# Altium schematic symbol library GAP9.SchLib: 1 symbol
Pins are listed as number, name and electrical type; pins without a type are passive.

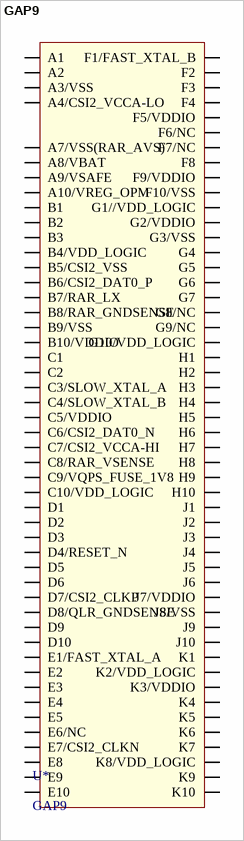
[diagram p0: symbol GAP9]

## GAP9
designator U*
footprint GAP9
pins: A1, A2, A3 A3/VSS, A4 A4/CSI2_VCCA-LO, A7 A7/VSS(RAR_AVS), A8 A8/VBAT, A9 A9/VSAFE, A10 A10/VREG_OPM, B1, B2, B3, B4 B4/VDD_LOGIC, B5 B5/CSI2_VSS, B6 B6/CSI2_DAT0_P, B7 B7/RAR_LX, B8 B8/RAR_GNDSENSE, B9 B9/VSS, B10 B10/VDDIO, C1, C2, C3 C3/SLOW_XTAL_A, C4 C4/SLOW_XTAL_B, C5 C5/VDDIO, C6 C6/CSI2_DAT0_N, C7 C7/CSI2_VCCA-HI, C8 C8/RAR_VSENSE, C9 C9/VQPS_FUSE_1V8, C10 C10/VDD_LOGIC, D1, D2, D3, D4 D4/RESET_N, D5, D6, D7 D7/CSI2_CLKP, D8 D8/QLR_GNDSENSE, D9, D10, E1 E1/FAST_XTAL_A, E2, E3, E4, E5, E6 E6/NC, E7 E7/CSI2_CLKN, E8, E9, E10, F1 F1/FAST_XTAL_B, F2, F3, F4, F5 F5/VDDIO, F6 F6/NC, F7 F7/NC, F8, F9 F9/VDDIO, F10 F10/VSS, G1 G1//VDD_LOGIC, G2 G2/VDDIO, G3 G3/VSS, G4, G5, G6, G7, G8 G8/NC, G9 G9/NC, G10 G10/VDD_LOGIC, H1, H2, H3, H4, H5, H6, H7, H8, H9, H10, J1, J2, J3, J4, J5, J6, J7 J7/VDDIO, J8 J8/VSS, J9, J10, K1, K2 K2/VDD_LOGIC, K3 K3/VDDIO, K4, K5, K6, K7, K8 K8/VDD_LOGIC, K9, K10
